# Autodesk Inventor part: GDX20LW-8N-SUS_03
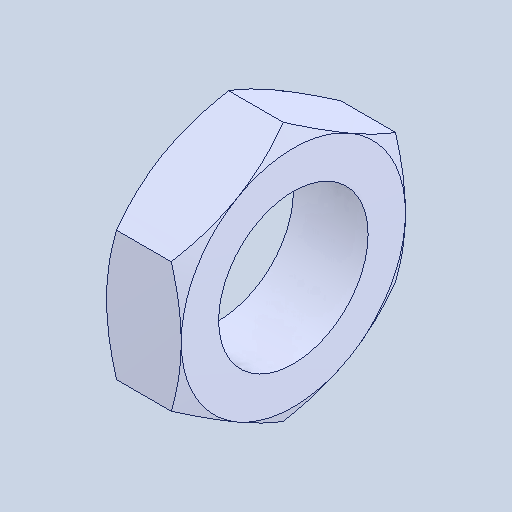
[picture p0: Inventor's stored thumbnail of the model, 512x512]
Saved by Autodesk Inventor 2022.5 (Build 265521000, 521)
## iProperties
Created: 2024-06
Part Number: GDX20LW-8N-SUS_03
Material: 一般
Document SubType Name: Modeling
Designer: ImaoCorp
Density: 1 g/cm^3
Appearance: 既定
Author: ImaoCorp
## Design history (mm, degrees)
feature "GDX20LW-8N-SUS_03"
node "ソリッド1"
